(* Logix 5000 project; controller Test vendor 1 type 14 code 92 rev 30.11; software revision 30.00 *)

TASK MainTask (continuous, watchdog 500 ms) : MainProgram

MODULES
   Local : vendor 1 type 14 code 92 (ICP 0, rev 30.11)
      IN : vendor 1 type 7 code 1 (ICP 3, rev 3.2, Input RPI 20 ms)
      O : vendor 1 type 7 code 15 (ICP 2, rev 3.2, Output RPI 20 ms)
      Ethernet : 1756-ENBT (ICP 1, Ethernet 192.168.0.98, rev 6.4)
         Banner_ABR1 : vendor 12 type 43 code 410 (Ethernet 192.168.0.150, rev 1.4, StandardDataDriven RPI 50 ms)
END_MODULES

TYPE Banner_ABR_IO_Data_Type :   // ABR AOI Data:
STRUCT
   InputBitsFromABR : SINT;   // The 8 bits used to receive the ABR's discrete output signals
   OutputBitsToABR : SINT;   // The 8 bits the ABR reads as inputs for control logic
   ItemStatus : INT;   // The current status code of the ABR
   FailureCode : SINT;   // The current failure code, if any. 0 = no failure.
   LastItemSeqNum : SINT;   // The 8-bit counter value for the last output message received from the ABR, goes up by 1 with each message received.
   LastItemData : STRING4096;   // The last output message received from the ABR
END_STRUCT
END_TYPE

TYPE STRING4096 :   // string type
STRUCT
   LEN : DINT;
   DATA : SINT[4096];
END_STRUCT
END_TYPE

ADD_ON_INSTRUCTION Banner_ABR_AOI_IO_Data   (* revision 2.0, vendor Banner Engineering *)
// AOI handles sequence number handshaking and fragment reassembly to put all the ABR barcode reader's implicit messaging data into named tags, including the latest full string.
VAR_IN_OUT
   RawDataFromABR : SINT[138]; {required}
   RawDataToABR : SINT[3]; {required}
   ABR_AOI_Tags : Banner_ABR_IO_Data_Type; {required}
END_VAR
VAR
   Reassembly_Buffer : SINT[4096]; {access None}   // Output message fragments from the ABR are put here for reassembling as they arrive before being copied into the LastItemData tag when all fragments have arrived.
   PLC_Total_Size_in_Buffer_After_Next_Copy : DINT; {access None}   // The calculated expected total size of the data in the reassembly buffer after the next fragment is entered.
   PLC_LastFragSeqNum : SINT; {access None}   // The last fraqment number the PLC took in from the ABR.
   ABR_ItemSeqNum : SINT; {access None}   // The latest sequence number of the last item the ABR sent data for
   ABR_ItemDataSize : INT; {access None}   // The total size of the output message being transmitted from the ABR.
   ABR_FragSeqNum : SINT; {access None}   // The last fragment sequence number of the data sent by the ABR
   ABR_FragDataSize : INT; {access None}   // The size of the last fragment sent by the ABR
   ABR_Power_Cycle_Oneshot : BOOL; {access None}
END_VAR

ROUTINE Logic   (* ladder *)
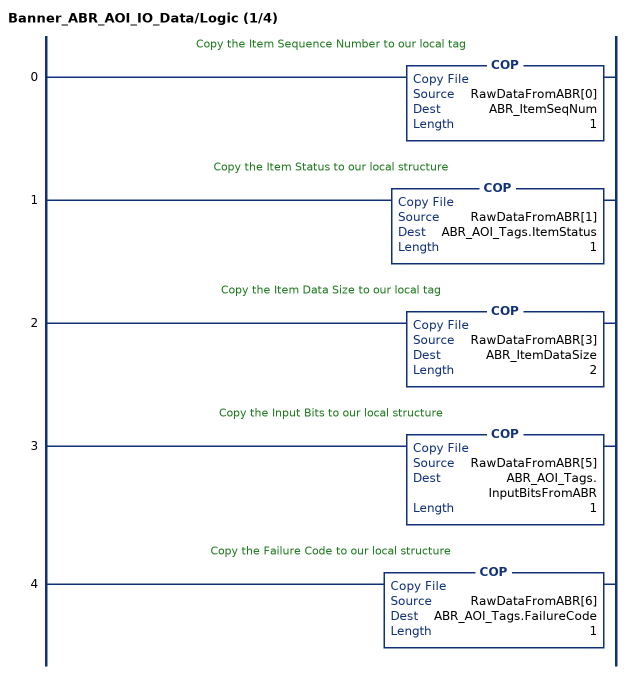
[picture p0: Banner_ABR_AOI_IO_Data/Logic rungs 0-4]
   // Copy the Item Sequence Number to our local tag
   0: COP(RawDataFromABR[0],ABR_ItemSeqNum,1);
   // Copy the Item Status to our local structure
   1: COP(RawDataFromABR[1],ABR_AOI_Tags.ItemStatus,1);
   // Copy the Item Data Size to our local tag
   2: COP(RawDataFromABR[3],ABR_ItemDataSize,2);
   // Copy the Input Bits to our local structure
   3: COP(RawDataFromABR[5],ABR_AOI_Tags.InputBitsFromABR,1);
   // Copy the Failure Code to our local structure
   4: COP(RawDataFromABR[6],ABR_AOI_Tags.FailureCode,1);
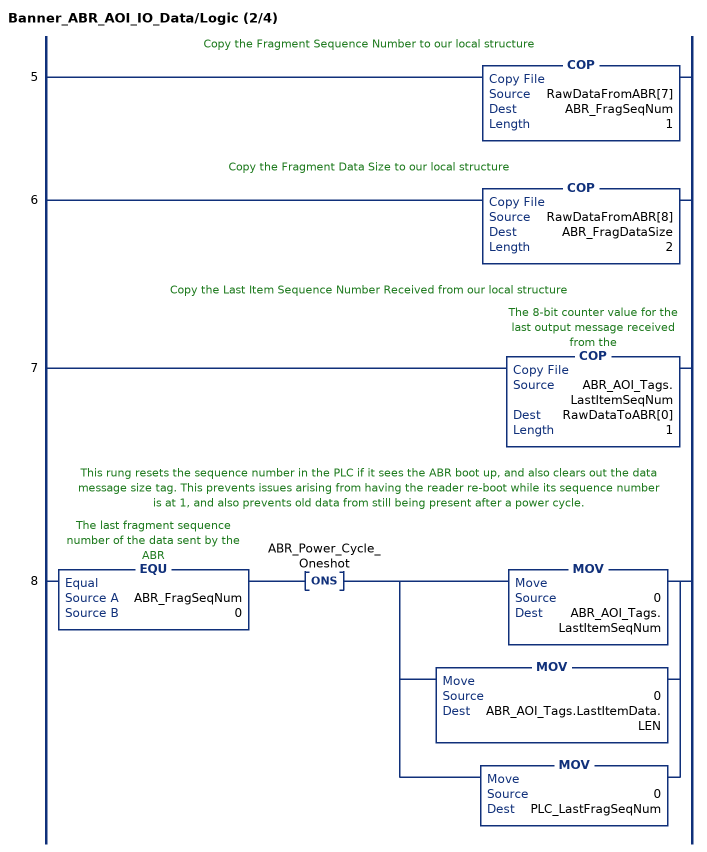
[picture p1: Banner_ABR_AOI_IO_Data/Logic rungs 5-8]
   // Copy the Fragment Sequence Number to our local structure
   5: COP(RawDataFromABR[7],ABR_FragSeqNum,1);
   // Copy the Fragment Data Size to our local structure
   6: COP(RawDataFromABR[8],ABR_FragDataSize,2);
   // Copy the Last Item Sequence Number Received from our local structure
   7: COP(ABR_AOI_Tags.LastItemSeqNum,RawDataToABR[0],1);
   // This rung resets the sequence number in the PLC if it sees the ABR boot up, and also clears out the data message size tag. This prevents issues arising from having the reader re-boot while its sequence number is at 1, and also prevents old data from still being present after a power cycle.
   8: EQU(ABR_FragSeqNum,0)ONS(ABR_Power_Cycle_Oneshot)[MOV(0,ABR_AOI_Tags.LastItemSeqNum) ,MOV(0,ABR_AOI_Tags.LastItemData.LEN) ,MOV(0,PLC_LastFragSeqNum) ];
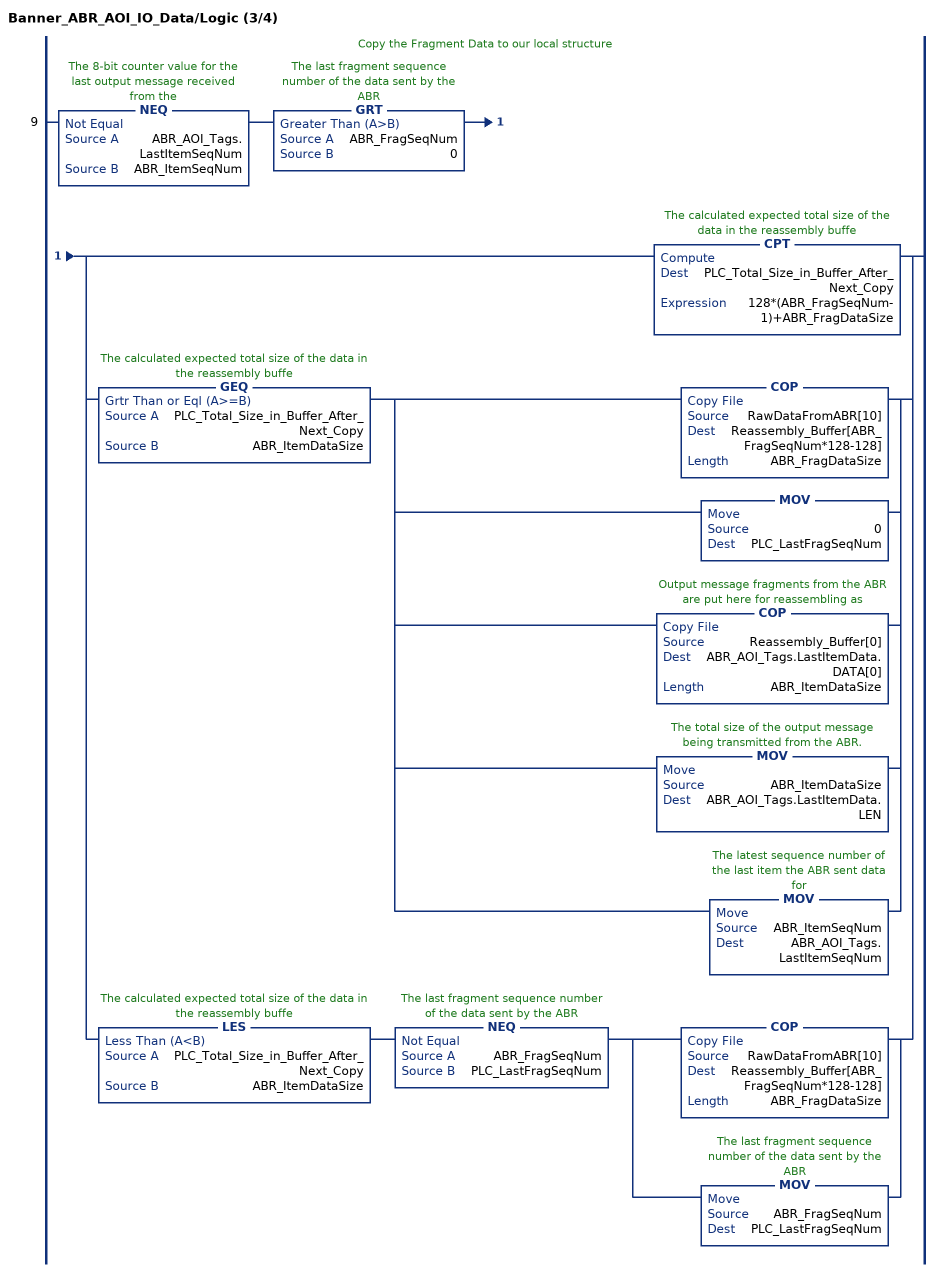
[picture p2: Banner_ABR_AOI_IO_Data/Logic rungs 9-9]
   // Copy the Fragment Data to our local structure
   9: NEQ(ABR_AOI_Tags.LastItemSeqNum,ABR_ItemSeqNum)GRT(ABR_FragSeqNum,0)[CPT(PLC_Total_Size_in_Buffer_After_Next_Copy,128*(ABR_FragSeqNum-1)+ABR_FragDataSize) ,GEQ(PLC_Total_Size_in_Buffer_After_Next_Copy,ABR_ItemDataSize) [COP(RawDataFromABR[10],Reassembly_Buffer[ABR_FragSeqNum*128-128],ABR_FragDataSize) ,MOV(0,PLC_LastFragSeqNum) ,COP(Reassembly_Buffer[0],ABR_AOI_Tags.LastItemData.DATA[0],ABR_ItemDataSize) ,MOV(ABR_ItemDataSize,ABR_AOI_Tags.LastItemData.LEN) ,MOV(ABR_ItemSeqNum,ABR_AOI_Tags.LastItemSeqNum) ] ,LES(PLC_Total_Size_in_Buffer_After_Next_Copy,ABR_ItemDataSize) NEQ(ABR_FragSeqNum,PLC_LastFragSeqNum) [COP(RawDataFromABR[10],Reassembly_Buffer[ABR_FragSeqNum*128-128],ABR_FragDataSize) ,MOV(ABR_FragSeqNum,PLC_LastFragSeqNum) ] ];
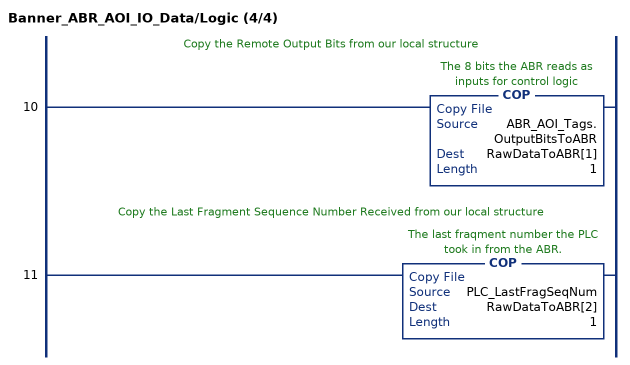
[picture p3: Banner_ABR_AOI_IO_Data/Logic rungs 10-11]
   // Copy the Remote Output Bits from our local structure
   10: COP(ABR_AOI_Tags.OutputBitsToABR,RawDataToABR[1],1);
   // Copy the Last Fragment Sequence Number Received from our local structure
   11: COP(PLC_LastFragSeqNum,RawDataToABR[2],1);
END_ROUTINE
END_ADD_ON_INSTRUCTION

VAR_GLOBAL   (* controller tags *)
   Banner_ABR1_AOI : Banner_ABR_AOI_IO_Data;
   Banner_ABR1_Tags : Banner_ABR_IO_Data_Type;
END_VAR

PROGRAM MainProgram   (* main routine MainRoutine *)

ROUTINE MainRoutine   (* ladder *)
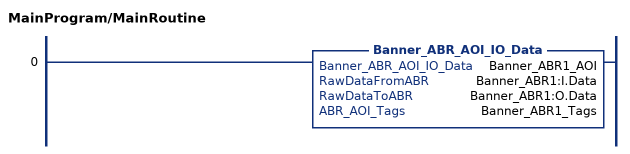
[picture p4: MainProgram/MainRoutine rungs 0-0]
   0: Banner_ABR_AOI_IO_Data(Banner_ABR1_AOI,Banner_ABR1:I.Data,Banner_ABR1:O.Data,Banner_ABR1_Tags);
END_ROUTINE
END_PROGRAM
